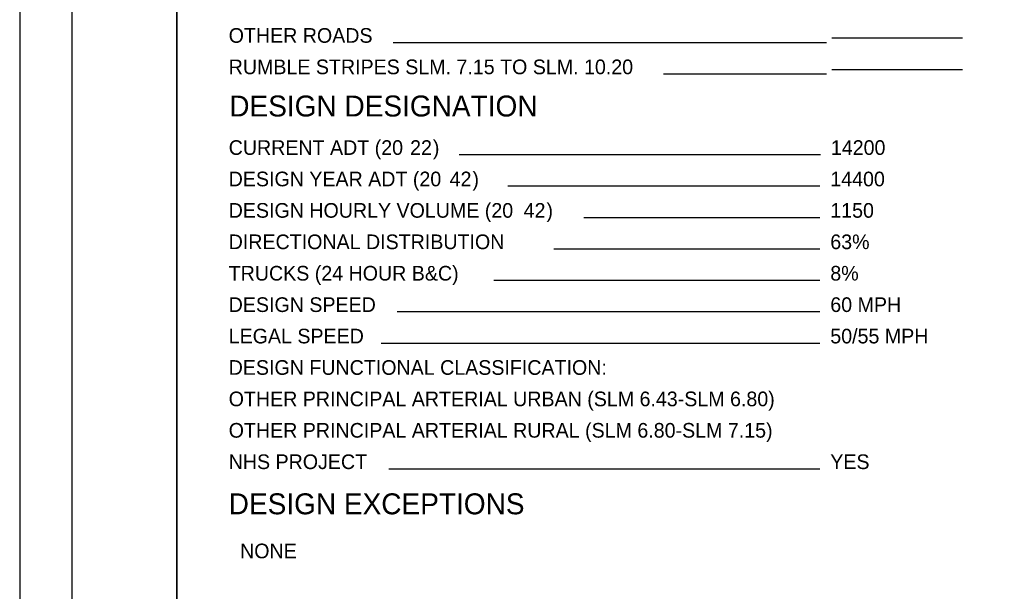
# Model space of a CAD drawing. Extents: x 0 to 34, y 0 to 22.
# Drawn here: x 0 to 9.43, y 5.64 to 11.1 of the extents above; entities that cross this region are included whole.
import ezdxf

# ---------------------------------------------------------------- set-up
doc = ezdxf.new("R2010")
doc.units = 0
for name, color, linetype in [('SH_Border', 7, 'Continuous'), ('SH_Cut_Line', 7, 'Continuous'), ('SH_Data', 7, 'Continuous'), ('SH_Text', 7, 'Continuous')]:
    doc.layers.add(name, color=color, linetype=linetype)

msp = doc.modelspace()

# ---------------------------------------------------------------- linework, layer by layer
at = {"layer": 'SH_Border'}
for points in [[(0.5, 21.5), (1.5, 21.5), (1.5, 0.5), (0.5, 0.5)], [(1.5, 21.5), (33.5, 21.5), (33.5, 0.5), (1.5, 0.5)]]:
    msp.add_lwpolyline(points, close=True, dxfattribs=at)
at = {"layer": 'SH_Cut_Line'}
msp.add_lwpolyline([(0, 0), (34, 0), (34, 22), (0, 22)], close=True, dxfattribs=at)
at = {"layer": 'SH_Data'}
for p, q in [((7.7, 10.8767), (3.5657, 10.8767)), ((9, 10.9223), (7.75, 10.9223)), ((7.7, 10.5767), (6.1438, 10.5767)), ((7.6424, 9.8062), (4.1936, 9.8062)), ((7.6368, 9.5062), (4.6592, 9.5062)), ((7.6368, 9.2062), (5.3852, 9.2062)), ((7.6368, 8.9062), (5.0988, 8.9062)), ((7.6368, 8.6062), (4.5259, 8.6062)), ((7.6368, 8.3062), (3.6035, 8.3062)), ((7.6368, 8.0062), (3.4488, 8.0062)), ((7.6368, 6.8062), (3.5243, 6.8062))]:
    msp.add_line(p, q, dxfattribs=at)
at = {"layer": 'SH_Text'}
msp.add_line((7.75, 10.6223), (9, 10.6223), dxfattribs=at)

# ---------------------------------------------------------------- texts
at = {"layer": 'SH_Data'}
msp.add_text('DESIGN DESIGNATION', height=0.2, dxfattribs=at).set_placement((2, 10.1729))
at = {"layer": 'SH_Text'}
for s, height, p in [('OTHER ROADS', 0.14, (1.9944, 10.8767)), ('RUMBLE STRIPES SLM. 7.15 TO SLM. 10.20', 0.14, (1.9944, 10.5767)), ('CURRENT ADT (20', 0.14, (1.9944, 9.8062)), ('22', 0.14, (3.7261, 9.8062)), (')', 0.14, (3.9435, 9.8062)), ('14200 ', 0.14, (7.7424, 9.8062)), ('DESIGN YEAR ADT (20', 0.14, (1.9944, 9.5062)), ('42', 0.14, (4.1033, 9.5062)), (')', 0.14, (4.3207, 9.5062)), ('14400 ', 0.14, (7.7368, 9.5062)), ('DESIGN HOURLY VOLUME (20', 0.14, (1.9944, 9.2062)), ('42', 0.14, (4.8099, 9.2062)), (')', 0.14, (5.0274, 9.2062)), ('1150  ', 0.14, (7.7368, 9.2062)), ('DIRECTIONAL DISTRIBUTION', 0.14, (1.9944, 8.9062)), ('63%   ', 0.14, (7.7368, 8.9062)), ('TRUCKS (24 HOUR B&C)', 0.14, (1.9944, 8.6062)), ('8%    ', 0.14, (7.7368, 8.6062)), ('DESIGN SPEED', 0.14, (1.9944, 8.3062)), ('60 MPH', 0.14, (7.7368, 8.3062)), ('LEGAL SPEED', 0.14, (1.9944, 8.0062)), ('50/55 MPH', 0.14, (7.7368, 8.0062)), ('DESIGN FUNCTIONAL CLASSIFICATION:', 0.14, (1.9944, 7.7062)), ('OTHER PRINCIPAL ARTERIAL URBAN (SLM 6.43-SLM 6.80)  ', 0.14, (1.9944, 7.4062)), ('OTHER PRINCIPAL ARTERIAL RURAL (SLM 6.80-SLM 7.15)  ', 0.14, (1.9944, 7.1062)), ('NHS PROJECT', 0.14, (1.9944, 6.8062)), ('YES   ', 0.14, (7.7368, 6.8062)), ('DESIGN EXCEPTIONS', 0.2, (1.9944, 6.3744)), ('NONE                                   ', 0.14, (2.103, 5.9544))]:
    msp.add_text(s, height=height, dxfattribs=at).set_placement(p)

doc.saveas('drawing.dxf')
